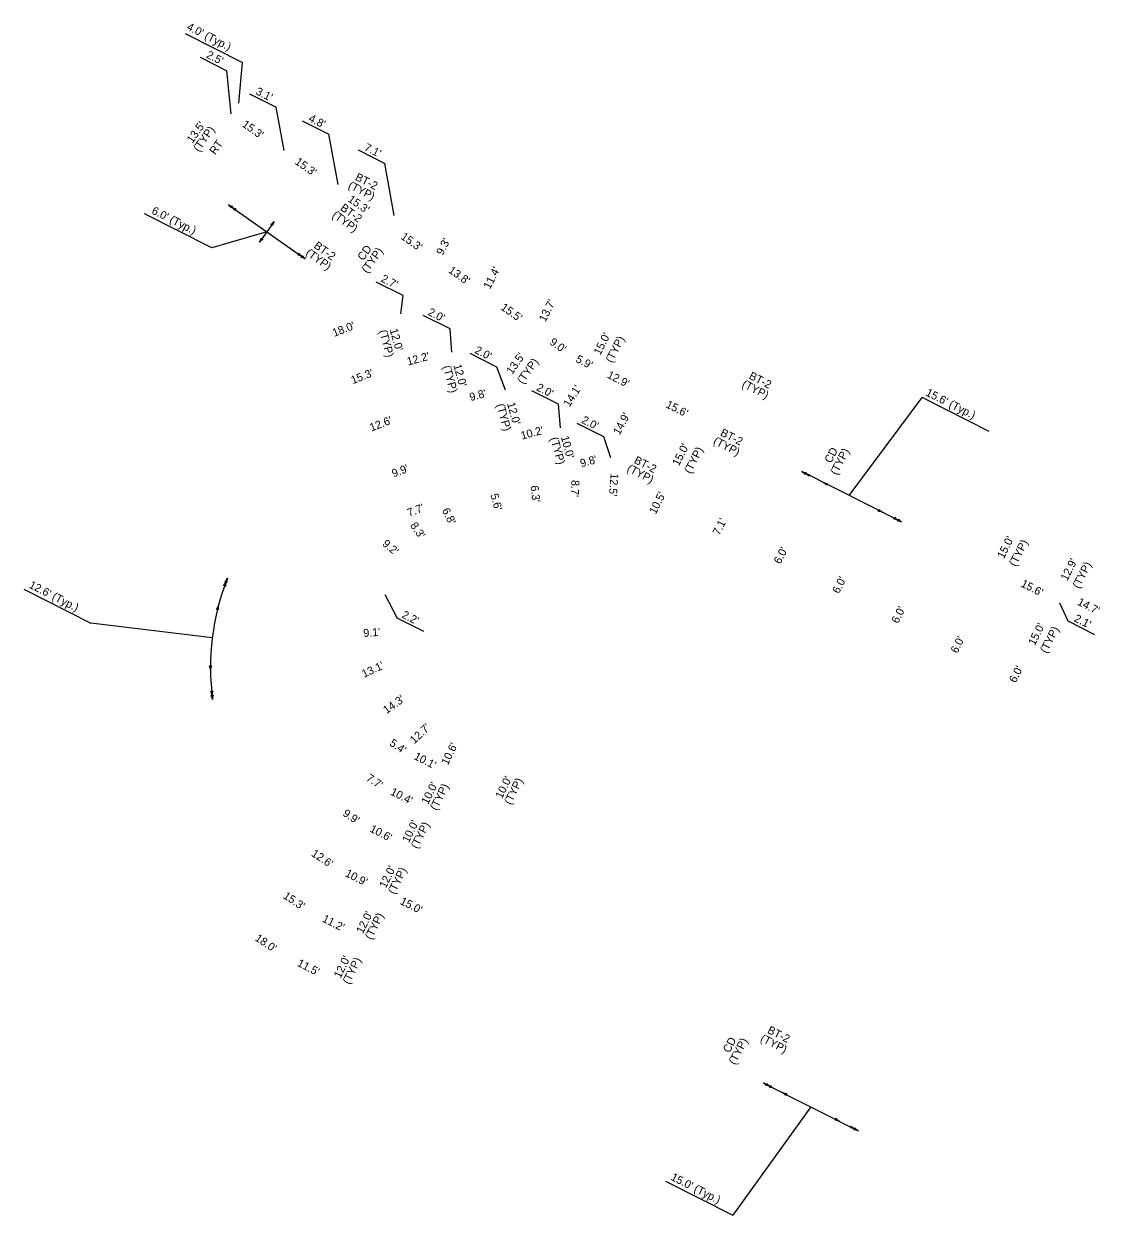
# Model space of a CAD drawing. Extents: x 15558215 to 15558792, y 8787373 to 8787891.
# Drawn here: x 15558214.6 to 15558468.7, y 8787609.4 to 8787890.6 of the extents above; entities that cross this region are included whole.
import ezdxf

# ---------------------------------------------------------------- set-up
doc = ezdxf.new("R2010")
doc.units = 0
doc.layers.add('Draft_Plan_Labels', color=7, linetype='Continuous')
doc.layers.add('Text', color=7, linetype='Continuous')

msp = doc.modelspace()

# ---------------------------------------------------------------- linework, layer by layer
at = {"layer": 'Draft_Plan_Labels'}
for p, q in [((15558262.94, 8787847.91), (15558263.34, 8787847.63)), ((15558262.94, 8787847.91), (15558263.73, 8787847.36)), ((15558263.73, 8787847.36), (15558264.12, 8787847.08)), ((15558263.73, 8787847.36), (15558264.51, 8787846.8)), ((15558273.73, 8787843.96), (15558273.17, 8787843.17)), ((15558273.73, 8787843.96), (15558273.45, 8787843.56)), ((15558270.26, 8787839.06), (15558270.82, 8787839.84)), ((15558270.26, 8787839.06), (15558270.54, 8787839.45)), ((15558280.26, 8787835.66), (15558279.48, 8787836.21)), ((15558280.26, 8787835.66), (15558279.87, 8787835.94)), ((15558281.05, 8787835.1), (15558280.26, 8787835.66)), ((15558281.05, 8787835.1), (15558280.65, 8787835.38)), ((15558398.29, 8787784.91), (15558398.72, 8787784.69)), ((15558398.29, 8787784.91), (15558399.15, 8787784.47)), ((15558399.15, 8787784.47), (15558399.58, 8787784.25)), ((15558399.15, 8787784.47), (15558400.01, 8787784.04)), ((15558403.36, 8787782.35), (15558403.8, 8787782.13)), ((15558403.36, 8787782.35), (15558404.22, 8787781.91)), ((15558417.33, 8787775.3), (15558416.47, 8787775.73)), ((15558417.33, 8787775.3), (15558416.9, 8787775.52)), ((15558421, 8787773.45), (15558420.14, 8787773.89)), ((15558421, 8787773.45), (15558420.56, 8787773.67)), ((15558421.85, 8787773.02), (15558421, 8787773.45)), ((15558421.85, 8787773.02), (15558421.42, 8787773.24)), ((15558262.34, 8787758.85), (15558262.01, 8787757.95)), ((15558262.34, 8787758.85), (15558262.17, 8787758.4)), ((15558262.69, 8787759.75), (15558262.34, 8787758.85)), ((15558262.69, 8787759.75), (15558262.51, 8787759.3)), ((15558260.57, 8787753.3), (15558260.33, 8787752.36)), ((15558260.57, 8787753.3), (15558260.45, 8787752.83)), ((15558258.68, 8787738.1), (15558258.68, 8787739.06)), ((15558258.68, 8787738.1), (15558258.68, 8787738.58)), ((15558259.06, 8787732.07), (15558258.96, 8787733.03)), ((15558259.06, 8787732.07), (15558259.01, 8787732.55)), ((15558259.18, 8787731.12), (15558259.06, 8787732.07)), ((15558259.18, 8787731.12), (15558259.12, 8787731.6)), ((15558389.27, 8787640.59), (15558389.7, 8787640.37)), ((15558389.27, 8787640.59), (15558390.13, 8787640.16)), ((15558390.13, 8787640.16), (15558390.56, 8787639.94)), ((15558390.13, 8787640.16), (15558390.99, 8787639.73)), ((15558393.73, 8787638.34), (15558394.17, 8787638.12)), ((15558393.73, 8787638.34), (15558394.59, 8787637.91)), ((15558407.13, 8787631.58), (15558406.27, 8787632.02)), ((15558407.13, 8787631.58), (15558406.69, 8787631.8)), ((15558410.73, 8787629.76), (15558409.87, 8787630.2)), ((15558410.73, 8787629.76), (15558410.3, 8787629.98)), ((15558411.59, 8787629.33), (15558410.73, 8787629.76)), ((15558411.59, 8787629.33), (15558411.16, 8787629.55))]:
    msp.add_line(p, q, dxfattribs=at)
for centre, radius, start, end in [((15558264.17, 8787849.65), 2.12, 234.7203, 262.7928), ((15558261.72, 8787846.18), 2.12, 26.6478, 54.7203), ((15558264.4, 8787846.88), 0.821, 126.9869, 162.4536), ((15558264.96, 8787849.09), 2.12, 234.7203, 262.7928), ((15558262.5, 8787845.62), 2.12, 26.6478, 54.7203), ((15558265.18, 8787846.33), 0.821, 126.9869, 162.4536), ((15558271.99, 8787845.18), 2.12, 296.6478, 324.7203), ((15558272.7, 8787842.5), 0.821, 36.9869, 72.4536), ((15558275.46, 8787842.73), 2.12, 144.7203, 172.7928), ((15558268.53, 8787840.29), 2.12, 324.7203, 352.7928), ((15558271.29, 8787840.51), 0.821, 216.9869, 252.4536), ((15558272, 8787837.83), 2.12, 116.6478, 144.7203), ((15558278.81, 8787836.69), 0.821, 306.9869, 342.4536), ((15558279.04, 8787833.92), 2.12, 54.7203, 82.7928), ((15558281.49, 8787837.39), 2.12, 206.6478, 234.7203), ((15558279.59, 8787836.13), 0.821, 306.9869, 342.4536), ((15558279.82, 8787833.37), 2.12, 54.7203, 82.7928), ((15558282.28, 8787836.84), 2.12, 206.6478, 234.7203), ((15558399.25, 8787786.8), 2.12, 243.2283, 271.3008), ((15558397.33, 8787783.01), 2.12, 35.1558, 63.2283), ((15558399.88, 8787784.1), 0.821, 135.495, 170.9617), ((15558400.11, 8787786.37), 2.12, 243.2283, 271.3008), ((15558398.19, 8787782.58), 2.12, 35.1558, 63.2283), ((15558400.74, 8787783.67), 0.821, 135.495, 170.9617), ((15558404.32, 8787784.24), 2.12, 243.2283, 271.3008), ((15558402.41, 8787780.45), 2.12, 35.1558, 63.2283), ((15558404.95, 8787781.54), 0.821, 135.495, 170.9617), ((15558415.74, 8787776.1), 0.821, 315.495, 350.9617), ((15558416.38, 8787773.4), 2.12, 63.2283, 91.3008), ((15558418.29, 8787777.2), 2.12, 215.1559, 243.2283), ((15558419.4, 8787774.26), 0.821, 315.495, 350.9617), ((15558420.04, 8787771.56), 2.12, 63.2283, 91.3008), ((15558421.95, 8787775.35), 2.12, 215.1559, 243.2283), ((15558420.26, 8787773.82), 0.821, 315.495, 350.9617), ((15558420.9, 8787771.12), 2.12, 63.2283, 91.3008), ((15558422.81, 8787774.92), 2.12, 215.1559, 243.2283), ((15558260.35, 8787759.59), 2.12, 311.8139, 339.8864), ((15558260.7, 8787760.52), 2.12, 310.8538, 338.9263), ((15558262.05, 8787758.09), 0.821, 51.1929, 86.6596), ((15558264.34, 8787758.12), 2.12, 159.8864, 187.9589), ((15558264.67, 8787758.99), 2.12, 158.9263, 186.9988), ((15558261.73, 8787757.18), 0.821, 52.153, 87.6197), ((15558258.51, 8787753.82), 2.12, 317.6458, 345.7182), ((15558262.63, 8787752.77), 2.12, 165.7182, 193.7907), ((15558260.13, 8787751.57), 0.821, 57.9849, 93.4516), ((15558258.68, 8787739.88), 0.821, 252.368, 287.8347), ((15558256.55, 8787738.09), 2.12, 0.1013, 28.1738), ((15558260.8, 8787738.1), 2.12, 152.0288, 180.1013), ((15558258.87, 8787733.84), 0.821, 258.4013, 293.868), ((15558256.95, 8787731.85), 2.12, 6.1346, 34.2071), ((15558258.96, 8787732.89), 0.821, 259.3614, 294.8281), ((15558257.07, 8787730.86), 2.12, 7.0947, 35.1672), ((15558261.17, 8787732.3), 2.12, 158.0621, 186.1346), ((15558261.29, 8787731.38), 2.12, 159.0222, 187.0947), ((15558390.23, 8787642.49), 2.12, 243.2283, 271.3008), ((15558388.31, 8787638.69), 2.12, 35.1558, 63.2283), ((15558390.86, 8787639.79), 0.821, 135.495, 170.9617), ((15558391.09, 8787642.06), 2.12, 243.2283, 271.3008), ((15558389.17, 8787638.26), 2.12, 35.1558, 63.2283), ((15558391.72, 8787639.36), 0.821, 135.495, 170.9617), ((15558394.69, 8787640.24), 2.12, 243.2283, 271.3008), ((15558392.78, 8787636.44), 2.12, 35.1558, 63.2283), ((15558395.32, 8787637.54), 0.821, 135.495, 170.9617), ((15558405.54, 8787632.39), 0.821, 315.495, 350.9617), ((15558408.08, 8787633.48), 2.12, 215.1559, 243.2283), ((15558406.17, 8787629.69), 2.12, 63.2283, 91.3008), ((15558409.14, 8787630.57), 0.821, 315.495, 350.9617), ((15558409.78, 8787627.87), 2.12, 63.2283, 91.3008), ((15558411.69, 8787631.66), 2.12, 215.1559, 243.2283), ((15558410, 8787630.13), 0.821, 315.495, 350.9617), ((15558410.63, 8787627.43), 2.12, 63.2283, 91.3008), ((15558412.55, 8787631.23), 2.12, 215.1559, 243.2283)]:
    msp.add_arc(centre, radius, start, end, dxfattribs=at)
at = {"layer": 'Text'}
for p, q in [((15558252.73, 8787888.3), (15558266.22, 8787881.5)), ((15558256.21, 8787882.71), (15558262.53, 8787879.52)), ((15558263.57, 8787869.32), (15558262.53, 8787879.52)), ((15558265.4, 8787871.9), (15558266.22, 8787881.5)), ((15558267.86, 8787874.09), (15558274.18, 8787870.9)), ((15558276.05, 8787860.68), (15558274.18, 8787870.9)), ((15558280.32, 8787867.72), (15558286.64, 8787864.54)), ((15558288.82, 8787852.65), (15558286.64, 8787864.54)), ((15558293.51, 8787860.84), (15558299.83, 8787857.65)), ((15558302.08, 8787845.35), (15558299.83, 8787857.65)), ((15558258.99, 8787837.75), (15558243.13, 8787845.75)), ((15558262.94, 8787847.91), (15558281.05, 8787835.1)), ((15558273.73, 8787843.96), (15558270.26, 8787839.06)), ((15558272, 8787841.51), (15558258.99, 8787837.75)), ((15558304.14, 8787826.46), (15558297.82, 8787829.65)), ((15558303.6, 8787822.12), (15558304.14, 8787826.46)), ((15558315.24, 8787818.6), (15558308.92, 8787821.78)), ((15558315.65, 8787813.07), (15558315.24, 8787818.6)), ((15558326.29, 8787809.59), (15558319.97, 8787812.78)), ((15558328.32, 8787804.11), (15558326.29, 8787809.59)), ((15558340.87, 8787800.79), (15558334.55, 8787803.98)), ((15558341.28, 8787795.27), (15558340.87, 8787800.79)), ((15558409.45, 8787779.28), (15558426.66, 8787802.41)), ((15558442.52, 8787794.41), (15558426.66, 8787802.41)), ((15558351.53, 8787793.12), (15558345.21, 8787796.3)), ((15558353.23, 8787788.17), (15558351.53, 8787793.12)), ((15558421.85, 8787773.02), (15558398.29, 8787784.91)), ((15558214.61, 8787757.17), (15558230.47, 8787749.17)), ((15558299.84, 8787755.88), (15558302.76, 8787750.33)), ((15558459.11, 8787753.9), (15558461.08, 8787749.68)), ((15558309.08, 8787747.14), (15558302.76, 8787750.33)), ((15558259.1, 8787745.66), (15558230.47, 8787749.17)), ((15558461.08, 8787749.68), (15558467.4, 8787746.49)), ((15558389.27, 8787640.59), (15558411.59, 8787629.33)), ((15558400.43, 8787634.96), (15558382, 8787609.4)), ((15558366.14, 8787617.4), (15558382, 8787609.4))]:
    msp.add_line(p, q, dxfattribs=at)
msp.add_arc((15558316.03, 8787738.68), 57.35, 158.4451, 187.5775, dxfattribs=at)

# ---------------------------------------------------------------- texts
for s, height, rotation, p in [("4.0' (Typ.)", 1.8898, 333.2283, (15558252.9, 8787889.3)), ("2.5'", 1.89, 333.3975, (15558257.53, 8787882.68)), ("3.1'", 1.89, 333.3975, (15558269.2, 8787874.05)), ("4.8'", 1.89, 333.3975, (15558281.66, 8787867.69)), ("13.5'", 1.89, 54.5511, (15558254.43, 8787862.27)), ('(TYP)', 1.89, 54.7203, (15558255.97, 8787860.24)), ("15.3'", 1.89, 324.7203, (15558265.98, 8787866.49)), ('RT', 1.89, 54.7203, (15558259.81, 8787859.56)), ("7.1'", 1.89, 333.3975, (15558294.81, 8787860.82)), ("15.3'", 1.89, 324.7203, (15558278.47, 8787857.66)), ('BT-2', 1.89, 332.9068, (15558292.67, 8787853.83)), ('(TYP)', 1.89, 332.9068, (15558291.01, 8787851.88)), ("15.3'", 1.89, 324.7203, (15558290.95, 8787848.82)), ("6.0' (Typ.)", 1.8898, 333.3975, (15558244.62, 8787845.89)), ('(TYP)', 1.89, 324.3988, (15558287.23, 8787845.1)), ('BT-2', 1.89, 324.3988, (15558289.16, 8787846.78)), ("15.3'", 1.89, 324.7203, (15558303.44, 8787839.99)), ("9.3'", 1.89, 63.0592, (15558313.53, 8787835.82)), ('(TYP)', 1.89, 324.3988, (15558280.98, 8787836.17)), ('BT-2', 1.89, 324.3988, (15558282.91, 8787837.85)), ('CD', 1.89, 54.7203, (15558294.76, 8787834.54)), ('(TYP)', 1.89, 54.7203, (15558295.71, 8787831.58)), ("13.8'", 1.89, 324.7203, (15558314.68, 8787832.04)), ("11.4'", 1.89, 63.0592, (15558324.66, 8787827.82)), ("2.7'", 1.89, 333.0592, (15558298.74, 8787829.85)), ("2.0'", 1.89, 333.0592, (15558309.83, 8787821.98)), ("15.5'", 1.89, 324.7203, (15558327.04, 8787823.29)), ("13.7'", 1.89, 63.0592, (15558337.75, 8787820.09)), ("18.0'", 1.89, 21.1534, (15558287.89, 8787816.69)), ('(TYP)', 1.89, 285.4473, (15558298.48, 8787818.1)), ("12.0'", 1.89, 285.4473, (15558300.98, 8787818.41)), ("15.0'", 1.89, 63.0592, (15558350.7, 8787812.26)), ("9.0'", 1.89, 324.7203, (15558338.58, 8787815.1)), ('(TYP)', 1.89, 63.0592, (15558353.52, 8787810.43)), ("12.2'", 1.89, 15.0622, (15558305.33, 8787809.94)), ("2.0'", 1.89, 333.0592, (15558320.89, 8787812.98)), ("13.5'", 1.89, 54.7203, (15558329.89, 8787807.69)), ("5.9'", 1.89, 332.9068, (15558344.74, 8787810.88)), ("15.3'", 1.89, 21.1534, (15558292.28, 8787805.52)), ('(TYP)', 1.89, 285.4473, (15558313.51, 8787809.68)), ("12.0'", 1.89, 285.4473, (15558316.01, 8787809.99)), ('(TYP)', 1.89, 54.7203, (15558332.42, 8787805.45)), ("12.9'", 1.89, 332.9068, (15558352.15, 8787807.15)), ('(TYP)', 1.89, 332.9068, (15558383.98, 8787804.98)), ('BT-2', 1.89, 332.9068, (15558385.64, 8787806.92)), ("9.8'", 1.89, 15.0622, (15558320.08, 8787801.54)), ("2.0'", 1.89, 333.0592, (15558335.46, 8787804.18)), ("14.1'", 1.89, 57.6818, (15558343.43, 8787800)), ("15.6' (Typ.)", 1.8898, 333.3975, (15558427.36, 8787802.95)), ('(TYP)', 1.89, 285.4473, (15558326.17, 8787800.68)), ("12.0'", 1.89, 285.4473, (15558328.67, 8787800.99)), ("15.6'", 1.89, 332.9068, (15558366.01, 8787800.16)), ("12.6'", 1.89, 21.1534, (15558296.68, 8787794.35)), ("2.0'", 1.89, 333.0592, (15558346.12, 8787796.5)), ("14.9'", 1.89, 61.6448, (15558355.25, 8787793.41)), ("10.2'", 1.89, 15.0622, (15558332.22, 8787792.44)), ('BT-2', 1.89, 332.9068, (15558378.87, 8787793.51)), ('(TYP)', 1.89, 285.4473, (15558338.89, 8787792.77)), ("10.0'", 1.89, 285.4473, (15558341.39, 8787793.08)), ('(TYP)', 1.89, 332.9068, (15558377.21, 8787791.56)), ("15.0'", 1.89, 63.0592, (15558369.26, 8787786.09)), ('(TYP)', 1.89, 63.0592, (15558372.08, 8787784.26)), ('CD', 1.89, 62.7464, (15558405.2, 8787786.75)), ('(TYP)', 1.89, 62.7464, (15558406.56, 8787783.95)), ("9.9'", 1.89, 21.1534, (15558301.91, 8787783.51)), ("9.8'", 1.89, 15.0622, (15558346.23, 8787785.92)), ('BT-2', 1.89, 332.9068, (15558358.5, 8787787.01)), ("12.5'", 1.89, 265.3786, (15558353.17, 8787784.56)), ('(TYP)', 1.89, 332.9068, (15558356.83, 8787785.07)), ("6.3'", 1.89, 276.356, (15558334.24, 8787781.56)), ("8.7'", 1.89, 267.2735, (15558343.91, 8787782.96)), ("5.6'", 1.89, 285.5855, (15558324.73, 8787779.43)), ("10.5'", 1.89, 63.2283, (15558363.78, 8787774.69)), ("7.7'", 1.89, 21.1534, (15558305.57, 8787774.21)), ("6.8'", 1.89, 296.9632, (15558313.25, 8787775.76)), ("8.3'", 1.89, 304.7152, (15558305.72, 8787772.19)), ("7.1'", 1.89, 63.2283, (15558378.8, 8787769.73)), ("15.0'", 1.89, 63.0592, (15558445.96, 8787764.2)), ("9.2'", 1.89, 319.9376, (15558299.08, 8787767.62)), ("6.0'", 1.89, 63.0592, (15558393.22, 8787762.93)), ('(TYP)', 1.89, 63.0592, (15558448.78, 8787762.37)), ("12.9'", 1.89, 63.0592, (15558460.94, 8787758.97)), ('(TYP)', 1.89, 63.0592, (15558463.76, 8787757.14)), ("12.6' (Typ.)", 1.8898, 333.0592, (15558215.65, 8787757.59)), ("6.0'", 1.89, 63.0592, (15558407.03, 8787755.96)), ("15.6'", 1.89, 332.9068, (15558449.82, 8787757.87)), ("6.0'", 1.89, 63.0592, (15558421, 8787748.91)), ("14.7'", 1.89, 332.9068, (15558463.17, 8787753.56)), ("2.2'", 1.89, 333.0592, (15558303.68, 8787750.53)), ("2.1'", 1.89, 333.3975, (15558462.4, 8787749.65)), ("9.1'", 1.89, 4.5297, (15558294.84, 8787745.84)), ("15.0'", 1.89, 63.0592, (15558453.27, 8787743.71)), ('(TYP)', 1.89, 63.0592, (15558456.09, 8787741.88)), ("6.0'", 1.89, 63.0592, (15558434.97, 8787741.86)), ("13.1'", 1.89, 24.8162, (15558294.93, 8787736.21)), ("6.0'", 1.89, 63.0592, (15558448.77, 8787734.9)), ("14.3'", 1.89, 35.2118, (15558300.25, 8787727.64)), ("12.7'", 1.89, 43.5302, (15558306.83, 8787720.54)), ("5.4'", 1.89, 326.012, (15558300.77, 8787720.41)), ("10.6'", 1.89, 63.7103, (15558314.72, 8787715.48)), ("10.1'", 1.89, 332.9068, (15558306.55, 8787717.12)), ("7.7'", 1.89, 326.012, (15558295.27, 8787712.16)), ("10.0'", 1.89, 63.7103, (15558310.03, 8787706.19)), ('(TYP)', 1.89, 63.7103, (15558312.1, 8787704.76)), ("10.0'", 1.89, 63.7103, (15558327.52, 8787707.55)), ('(TYP)', 1.89, 63.7103, (15558329.59, 8787706.12)), ("10.4'", 1.89, 332.9068, (15558300.99, 8787708.74)), ("9.9'", 1.89, 326.012, (15558289.73, 8787703.83)), ("10.0'", 1.89, 63.7103, (15558305.49, 8787697.16)), ("10.6'", 1.89, 332.9068, (15558296.11, 8787700)), ('(TYP)', 1.89, 63.7103, (15558307.56, 8787695.73)), ("12.6'", 1.89, 326.012, (15558282.33, 8787694.35)), ("12.0'", 1.89, 63.7103, (15558300.08, 8787686.43)), ('(TYP)', 1.89, 63.7103, (15558302.15, 8787685)), ("10.9'", 1.89, 332.9068, (15558290.31, 8787689.49)), ("15.3'", 1.89, 326.012, (15558275.67, 8787684.36)), ("15.0'", 1.89, 332.9068, (15558303.27, 8787682.94)), ("11.2'", 1.89, 332.9068, (15558284.89, 8787678.78)), ("12.0'", 1.89, 63.7103, (15558294.66, 8787675.69)), ('(TYP)', 1.89, 63.7103, (15558296.73, 8787674.26)), ("18.0'", 1.89, 326.012, (15558269.02, 8787674.38)), ("11.5'", 1.89, 332.9068, (15558278.99, 8787668.31)), ("12.0'", 1.89, 63.7103, (15558289.36, 8787665.18)), ('(TYP)', 1.89, 63.7103, (15558291.43, 8787663.75)), ('(TYP)', 1.89, 332.9068, (15558388.32, 8787650.55)), ('BT-2', 1.89, 332.9068, (15558389.98, 8787652.49)), ('CD', 1.89, 62.7464, (15558381.21, 8787647.55)), ('(TYP)', 1.89, 62.7464, (15558382.57, 8787644.75)), ("15.0' (Typ.)", 1.8898, 333.0592, (15558367.18, 8787617.81))]:
    msp.add_text(s, height=height, rotation=rotation, dxfattribs=at).set_placement(p)

doc.saveas('drawing.dxf')
